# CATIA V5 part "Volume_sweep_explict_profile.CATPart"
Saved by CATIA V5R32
Part number: Part1
Bounding box of the stored display mesh (mm): x -27.367 to 27.367, y -27.346 to 38.443, z 0 to 133.822
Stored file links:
  D:\PROJECTS\Project 2022\CATIA V5 6R 2022\Resources\Part Files\c17_catia_v6_6r2022_prt\Volume_sweep_explict_profile.CATPart
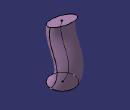
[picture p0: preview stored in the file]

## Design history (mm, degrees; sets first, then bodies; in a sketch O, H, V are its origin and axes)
Set1
  Sketch1 on xy-plane, origin (0, 0, 0), H (1, 0, 0), V (0, 1, 0)
    circle A1 centre (0, 0) radius 27.367
  Sketch2 on yz-plane, origin (0, 0, 0), H (0, 1, 0), V (0, 0, 1)
    spline S1 through (0, 0) (11.9407, 56.843) (-3.4307, 102.6672) (-1.4005, 123.8391)
    point P1 (0, 0)
    coincidence: P1 O
  Sweep1: type Unspec, Profile Sketch1, Guide Sketch2
Body1 (main body)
